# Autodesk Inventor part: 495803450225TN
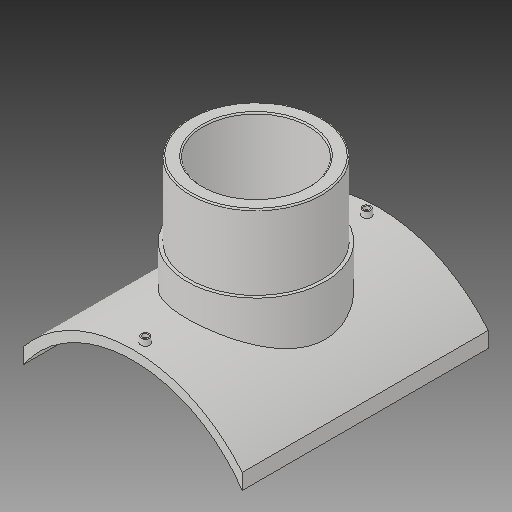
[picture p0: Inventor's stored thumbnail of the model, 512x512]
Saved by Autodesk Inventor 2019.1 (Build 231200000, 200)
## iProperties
Created: 2017-10
Part Number: 495803450225TN
Material: Generic
Description: PLASSON BRANCH SADDLE  400-450x225
Document SubType Name: Modeling
Designer: KIM
Mass: 2754.05 g
Surface Area: 3037.44 cm^2
Volume: 2754.05 cm^3
Density: 1 g/cm^3
Appearance: Default
Author: KIM
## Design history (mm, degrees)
derived "495803.ipt"
feature "Solid1::495803.ipt"
tag "TaggingFeature1"
body "Solid1"
other parameters: "d1" = 16, "d2" = 373, "d4" = 0, "d12" = 250.6, "d13" = 14, "d14" = 189, "d16" = 5 deg, "d18" = 4, "d19" = 14, "d20" = 0, "d21" = 3, "d22" = 0, "d23" = 423, "d24" = 236.25, "d25" = 16, "d28" = 0, "d29" = 9.6, "d31" = 0, "d32" = 91, "d33" = 0, "d34" = 4.5, "d36" = 225, "d37" = 127.4, "d38" = 0, "d39" = 2.25, "d_1" = 225, "B_" = 373, "H_" = 182, "x_" = 16, "D_" = 16
